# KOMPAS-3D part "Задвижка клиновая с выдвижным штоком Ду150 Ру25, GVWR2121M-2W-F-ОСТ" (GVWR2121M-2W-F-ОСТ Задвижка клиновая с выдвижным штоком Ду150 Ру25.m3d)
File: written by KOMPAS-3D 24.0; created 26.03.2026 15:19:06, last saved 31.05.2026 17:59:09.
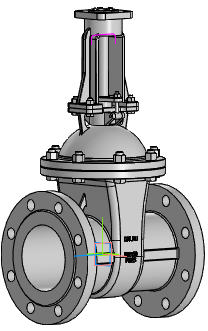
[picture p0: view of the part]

Document properties: Автор: R2D2; Полное имя файла: E:\Работа\Зайцев\GVWR2121M-2W-F-ОСТ Задвижка клиновая 30с964нж DN.ru Ду50-300 Ру25\исходные материалы\DN150\GVWR2121M-2W-F-ОСТ Задвижка клиновая с выдвижным штоком Ду150 Ру25.m3d

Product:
- Component [detail]: ANSI B18.2.4.2M - M16x2 - 24  | designation ANSI B18.2.4.2M - M16x2  | qty 8  | pos. 2  | Комментарий: Типы метрических   шестигранных гаек   2; Автор: R2D2; additional columns: Сталь, мягкая; source file: ANSI B18.2.4.2M - M16x2 ANSI B18.2.4.2M - M16x2 - 24.m3d
- Component [detail]: AS 1110 - M16 x 60  | qty 8  | pos. 3  | Комментарий: Болты и винты   шестигранные точные   метрические ISO; Автор: R2D2; additional columns: Сталь, мягкая; source file: AS 1110 - M16 x 60 AS 1110 - M16 x 60.m3d
- Component [detail]: AS 1110 - M10 x 35  | qty 4  | pos. 4  | Комментарий: Болты и винты   шестигранные точные   метрические ISO; Автор: R2D2; additional columns: Сталь, мягкая; source file: AS 1110 - M10 x 35 AS 1110 - M10 x 35.m3d
- Component [detail]: ANSI B18.2.4.2M - M10x1,5 - 16  | designation ANSI B18.2.4.2M - M10x1,5  | qty 4  | pos. 5  | Комментарий: Типы метрических   шестигранных гаек   2; Автор: R2D2; additional columns: Сталь, мягкая; source file: ANSI B18.2.4.2M - M10x1,5 ANSI B18.2.4.2M - M10x1,5 - 16.m3d
- Component [detail]: ANSI B18.2.4.2M - M8x1,25 - 13  | designation ANSI B18.2.4.2M - M8x1,25  | qty 1  | pos. 6  | Комментарий: Типы метрических   шестигранных гаек   2; Автор: R2D2; additional columns: Сталь, мягкая; source file: ANSI B18.2.4.2M - M8x1,25 ANSI B18.2.4.2M - M8x1,25 - 13.m3d
- Component [detail]: Деталь1  | qty 1  | pos. 7  | Автор: R2D2; additional columns: Типовые; source file: 2.m3d
- Component [detail]: Фланец  | qty 1  | pos. 8  | Автор: R2D2; additional columns: Типовые; source file: Фланец DN150 PN25 b30.m3d
- Component [detail]: Фланец  | qty 1  | pos. 9  | Автор: R2D2; additional columns: Типовые; source file: Фланец DN150 PN25 b30.m3d
- Component [detail]: ANSI B18.2.4.2M - M8x1,25 - 13  | designation ANSI B18.2.4.2M - M8x1,25-01  | qty 1  | pos. 6  | Комментарий: Типы метрических   шестигранных гаек   2; Автор: R2D2; additional columns: Сталь, мягкая; source file: ANSI B18.2.4.2M - M8x1,25 ANSI B18.2.4.2M - M8x1,25 - 13.m3d
- Component [assembly]: DN50_3D_STEP  | designation Сборка  | qty 1  | Масса: 2.725126; Автор: R2D2; source file: Фланец А.a3d
- Body: Тело 1  | qty 1
    Масса: 107.979176
- Body: Тело 2  | qty 1
    Масса: 107.979176
- Part/product: Задвижка клиновая с выдвижным штоком Ду150 Ру25  | designation GVWR2121M-2W-F-ОСТ
    Масса: 60
    Раздел спецификации: Прочие изделия
    Примечание: D040-08602
    additional columns: D040-10013

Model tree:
1. Массив по сетке:2  (labels: Грань.Твердое тело1; Вершина.Твердое тело1)  (4 pattern instances)
     Шаг 1 = 50; Угол раствора = 90; Шаг 2 = 120
2. Массив по концентрической сетке:1  (labels: Грань.Твердое тело1)  (8 pattern instances)
     Шаг 2 = 360
3. Элемент выдавливания:1  (with: Грань.Элемент выдавливания:2, Грань.Элемент вращения:1)
     Расстояние 1 = 36.9829
4. Элемент выдавливания:2  (with: Грань.Элемент выдавливания:1, Грань.Элемент вращения:1)
     Расстояние 1 = 38.9519
5. Скругление:1  (with: Ребро.Элемент выдавливания:2, Ребро.Элемент выдавливания:1)
     Радиус = 3
6. Элемент выдавливания:3  (with: Грань.Элемент выдавливания:1)
     Расстояние 1 = 60
7. Эскиз:1  (with: Вершина.Элемент выдавливания:3, Ребро.Операция без истории:2, Ребро.Элемент выдавливания:1)
8. Элемент по траектории:1  (with: Грань.Элемент выдавливания:3)
     Длина траектории = 108.92
9. Элемент выдавливания:4  (with: Грань.Элемент выдавливания:1, Грань.Элемент по траектории:1)
     Расстояние 1 = 134.696
10. Эскиз:2
11. Элемент выдавливания:5  (with: Грань.Элемент выдавливания:1, Грань.Элемент вращения:1, Грань.Операция без истории:2)  (labels: Грань.Твердое тело1; Грань.Solid1; Solid1; Твердое тело1)
     Расстояние 1 = 98.5; Смещение 1 = 1; Расстояние = -175; Ориентация = 2; Ориентация = 2; Расстояние = -550

Referenced files in E:\Работа\Зайцев\GVWR2121M-2W-F-ОСТ Задвижка клиновая 30с964нж DN.ru Ду50-300 Ру25\исходные материалы\DN150\: ANSI B18.2.4.2M - M16x2 ANSI B18.2.4.2M - M16x2 - 24.m3d, AS 1110 - M16 x 60 AS 1110 - M16 x 60.m3d, AS 1110 - M10 x 35 AS 1110 - M10 x 35.m3d, ANSI B18.2.4.2M - M10x1,5 ANSI B18.2.4.2M - M10x1,5 - 16.m3d, ANSI B18.2.4.2M - M8x1,25 ANSI B18.2.4.2M - M8x1,25 - 13.m3d, 2.m3d, Фланец DN150 PN25 b30.m3d, Фланец А.a3d
Referenced files in E:\Работа\Зайцев\GVWR2434M-2W-F-ОСТ Задвижка клиновая с выдвижным штоком DN.ru Ду50-300 Ру25\исходные материалы\DN150\: Фланец DN150 PN25 b30.m3d
Referenced files in E:\Работа\Зайцев\GVWR3131M-2W-F-S Задвижка клиновая с выдвижным штоком DN.ru Ду50-200 Ру63\DN150\исходные материалы\: ANSI B18.2.4.2M - M10x1,5 ANSI B18.2.4.2M - M10x1,5 - 16.m3d, ANSI B18.2.4.2M - M16x2 ANSI B18.2.4.2M - M16x2 - 24.m3d, AS 1110 - M10 x 35 AS 1110 - M10 x 35.m3d, AS 1110 - M16 x 60 AS 1110 - M16 x 60.m3d
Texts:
  GVWR2121M-2W-F-ОСТ
  DN150
  GOST 26.020 Pr3
  PN25
  ANSI B18.2.4.2M - M16x2 ANSI B18.2.4.2M - M16x2 - 24 (1)
  AS 1110 - M16 x 60 AS 1110 - M16 x 60 (1)
  AS 1110 - M10 x 35 AS 1110 - M10 x 35 (1)
  ANSI B18.2.4.2M - M10x1,5 ANSI B18.2.4.2M - M10x1,5 - 16 (1)
  ANSI B18.2.4.2M - M8x1,25 ANSI B18.2.4.2M - M8x1,25 - 13
  Деталь1 Деталь1
  Фланец (1)
  Фланец (2)
  ANSI B18.2.4.2M - M10x1,5 ANSI B18.2.4.2M - M10x1,5 - 16 (2)
  ANSI B18.2.4.2M - M16x2 ANSI B18.2.4.2M - M16x2 - 24 (2)
  AS 1110 - M10 x 35 AS 1110 - M10 x 35 (2)
  ANSI B18.2.4.2M - M8x1,25-01 ANSI B18.2.4.2M - M8x1,25 - 13
  ANSI B18.2.4.2M - M10x1,5 ANSI B18.2.4.2M - M10x1,5 - 16 (3)
  AS 1110 - M16 x 60 AS 1110 - M16 x 60 (2)
  AS 1110 - M10 x 35 AS 1110 - M10 x 35 (3)
  Сборка DN50_3D_STEP
  ANSI B18.2.4.2M - M10x1,5 ANSI B18.2.4.2M - M10x1,5 - 16 (4)
  ANSI B18.2.4.2M - M16x2 ANSI B18.2.4.2M - M16x2 - 24 (3)
  AS 1110 - M10 x 35 AS 1110 - M10 x 35 (4)
  AS 1110 - M16 x 60 AS 1110 - M16 x 60 (3)
  ANSI B18.2.4.2M - M16x2 ANSI B18.2.4.2M - M16x2 - 24 (4)
  AS 1110 - M16 x 60 AS 1110 - M16 x 60 (4)
  ANSI B18.2.4.2M - M16x2 ANSI B18.2.4.2M - M16x2 - 24 (5)
  AS 1110 - M16 x 60 AS 1110 - M16 x 60 (5)
  ANSI B18.2.4.2M - M16x2 ANSI B18.2.4.2M - M16x2 - 24 (6)
  AS 1110 - M16 x 60 AS 1110 - M16 x 60 (6)
  ANSI B18.2.4.2M - M16x2 ANSI B18.2.4.2M - M16x2 - 24 (7)
  AS 1110 - M16 x 60 AS 1110 - M16 x 60 (7)
  ANSI B18.2.4.2M - M16x2 ANSI B18.2.4.2M - M16x2 - 24 (8)
  AS 1110 - M16 x 60 AS 1110 - M16 x 60 (8)
  Ось Z.Начало координат
  Ось Y.Начало координат
  Плоскость ZY.Начало координат
  Плоскость ZX.Начало координат
  Плоскость XY.Начало координат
